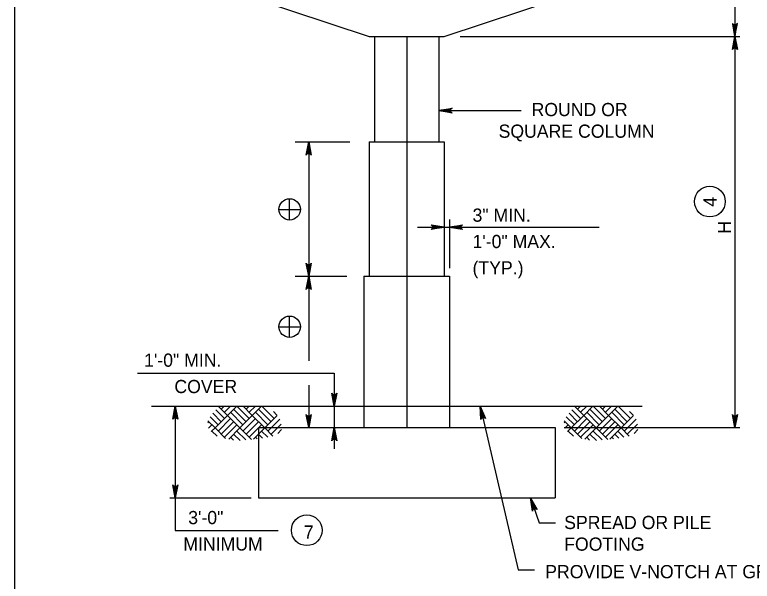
# Model space of a CAD drawing. Extents: x 646165 to 651486, y 296916 to 299292.
# Drawn here: x 649829.6 to 649997.2, y 299095.6 to 299224.4 of the extents above; entities that cross this region are included whole.
import ezdxf

# ---------------------------------------------------------------- set-up
doc = ezdxf.new("R2010")
doc.units = 0
for name, color, linetype in [('2', 7, 'Continuous'), ('34', 7, 'Continuous'), ('50', 7, 'Continuous'), ('51', 7, 'Continuous'), ('52', 7, 'Continuous'), ('53', 7, 'Continuous'), ('54', 7, 'Continuous'), ('56', 7, 'Continuous')]:
    doc.layers.add(name, color=color, linetype=linetype)

msp = doc.modelspace()

# ---------------------------------------------------------------- linework, layer by layer
at = {"layer": '2'}
msp.add_line((649829.59, 298713.25), (649829.59, 299277.25), dxfattribs=at)
at = {"layer": '34'}
msp.add_line((649860.66, 299135.38), (649972.19, 299135.38), dxfattribs=at)
at = {"layer": '50'}
msp.add_line((649918.68, 299219.49), (649918.68, 299130.5), dxfattribs=at)
at = {"layer": '51'}
for p, q in [((649870.68, 299232.6), (649910.16, 299219.49)), ((649927.2, 299219.49), (649966.68, 299232.6)), ((649910.16, 299219.49), (649927.2, 299219.49)), ((649911.36, 299219.49), (649911.36, 299195.49)), ((649926, 299219.49), (649926, 299195.49)), ((649910.16, 299195.49), (649927.2, 299195.49)), ((649910.16, 299195.49), (649910.16, 299164.93)), ((649927.2, 299195.49), (649927.2, 299164.93)), ((649908.96, 299164.93), (649908.96, 299130.5)), ((649908.96, 299164.93), (649928.4, 299164.93)), ((649928.4, 299164.93), (649928.4, 299130.5)), ((649884.96, 299130.5), (649952.41, 299130.5)), ((649884.96, 299130.5), (649884.96, 299114.5)), ((649952.41, 299130.5), (649952.41, 299114.5)), ((649884.96, 299114.5), (649952.41, 299114.5))]:
    msp.add_line(p, q, dxfattribs=at)
at = {"layer": '52'}
for p, q in [((649993.28, 299245.71), (649993.28, 299130.5)), ((649930.87, 299219.49), (649994.38, 299219.49)), ((649893.3, 299195.49), (649905.77, 299195.49)), ((649896.4, 299195.49), (649896.4, 299164.93)), ((649928.4, 299177.87), (649928.4, 299166.82)), ((649921.17, 299176.11), (649962.4, 299176.11)), ((649893.3, 299164.93), (649905.04, 299164.93)), ((649896.4, 299164.93), (649896.4, 299145.67)), ((649857.5, 299142.93), (649902.21, 299142.93)), ((649902.21, 299142.93), (649902.21, 299125.7)), ((649896.4, 299140.16), (649896.4, 299130.5)), ((649866.09, 299135.38), (649866.09, 299107.11)), ((649954.44, 299130.5), (649994.38, 299130.5)), ((649864.85, 299114.5), (649883.32, 299114.5)), ((649866.09, 299107.11), (649889.46, 299107.11))]:
    msp.add_line(p, q, dxfattribs=at)
for points in [[(649993.28, 299219.49), (649993.84, 299222.47), (649993.76, 299222.36), (649993.68, 299222.24), (649993.58, 299222.18), (649993.48, 299222.12), (649993.38, 299222.11), (649993.28, 299222.09), (649993.18, 299222.11), (649993.08, 299222.12), (649992.98, 299222.18), (649992.88, 299222.24), (649992.8, 299222.36), (649992.72, 299222.47), (649993.28, 299219.49), (649992.8, 299222.36), (649992.88, 299222.24), (649993.28, 299219.49), (649992.98, 299222.18), (649993.08, 299222.12), (649993.28, 299219.49), (649993.18, 299222.11), (649993.28, 299222.09), (649993.28, 299219.49), (649993.38, 299222.11), (649993.48, 299222.12), (649993.28, 299219.49), (649993.58, 299222.18), (649993.68, 299222.24), (649993.28, 299219.49), (649993.76, 299222.36)], [(649993.28, 299219.49), (649993.84, 299216.51), (649993.76, 299216.62), (649993.68, 299216.74), (649993.58, 299216.79), (649993.48, 299216.85), (649993.38, 299216.87), (649993.28, 299216.89), (649993.18, 299216.87), (649993.08, 299216.85), (649992.98, 299216.79), (649992.88, 299216.74), (649992.8, 299216.62), (649992.72, 299216.51), (649993.28, 299219.49), (649992.8, 299216.62), (649992.88, 299216.74), (649993.28, 299219.49), (649992.98, 299216.79), (649993.08, 299216.85), (649993.28, 299219.49), (649993.18, 299216.87), (649993.28, 299216.89), (649993.28, 299219.49), (649993.38, 299216.87), (649993.48, 299216.85), (649993.28, 299219.49), (649993.58, 299216.79), (649993.68, 299216.74), (649993.28, 299219.49), (649993.76, 299216.62)], [(649926, 299202.64), (649928.99, 299203.2), (649928.87, 299203.12), (649928.76, 299203.04), (649928.7, 299202.94), (649928.64, 299202.84), (649928.62, 299202.74), (649928.6, 299202.64), (649928.62, 299202.54), (649928.64, 299202.44), (649928.7, 299202.34), (649928.76, 299202.24), (649928.87, 299202.16), (649928.99, 299202.08), (649926, 299202.64), (649928.87, 299202.16), (649928.76, 299202.24), (649926, 299202.64), (649928.7, 299202.34), (649928.64, 299202.44), (649926, 299202.64), (649928.62, 299202.54), (649928.6, 299202.64), (649926, 299202.64), (649928.62, 299202.74), (649928.64, 299202.84), (649926, 299202.64), (649928.7, 299202.94), (649928.76, 299203.04), (649926, 299202.64), (649928.87, 299203.12)], [(649926, 299202.64), (649944.71, 299202.64)], [(649896.4, 299195.49), (649896.96, 299192.51), (649896.88, 299192.62), (649896.8, 299192.73), (649896.7, 299192.79), (649896.6, 299192.85), (649896.5, 299192.87), (649896.4, 299192.89), (649896.3, 299192.87), (649896.2, 299192.85), (649896.1, 299192.79), (649896, 299192.73), (649895.92, 299192.62), (649895.84, 299192.51), (649896.4, 299195.49), (649895.92, 299192.62), (649896, 299192.73), (649896.4, 299195.49), (649896.1, 299192.79), (649896.2, 299192.85), (649896.4, 299195.49), (649896.3, 299192.87), (649896.4, 299192.89), (649896.4, 299195.49), (649896.5, 299192.87), (649896.6, 299192.85), (649896.4, 299195.49), (649896.7, 299192.79), (649896.8, 299192.73), (649896.4, 299195.49), (649896.88, 299192.62)], [(649927.2, 299176.11), (649924.22, 299175.55), (649924.33, 299175.63), (649924.45, 299175.71), (649924.51, 299175.81), (649924.57, 299175.91), (649924.59, 299176.01), (649924.6, 299176.11), (649924.59, 299176.21), (649924.57, 299176.31), (649924.51, 299176.41), (649924.45, 299176.51), (649924.33, 299176.59), (649924.22, 299176.67), (649927.2, 299176.11), (649924.33, 299176.59), (649924.45, 299176.51), (649927.2, 299176.11), (649924.51, 299176.41), (649924.57, 299176.31), (649927.2, 299176.11), (649924.59, 299176.21), (649924.6, 299176.11), (649927.2, 299176.11), (649924.59, 299176.01), (649924.57, 299175.91), (649927.2, 299176.11), (649924.51, 299175.81), (649924.45, 299175.71), (649927.2, 299176.11), (649924.33, 299175.63)], [(649928.4, 299176.11), (649931.39, 299176.67), (649931.27, 299176.59), (649931.16, 299176.51), (649931.1, 299176.41), (649931.04, 299176.31), (649931.02, 299176.21), (649931, 299176.11), (649931.02, 299176.01), (649931.04, 299175.91), (649931.1, 299175.81), (649931.16, 299175.71), (649931.27, 299175.63), (649931.39, 299175.55), (649928.4, 299176.11), (649931.27, 299175.63), (649931.16, 299175.71), (649928.4, 299176.11), (649931.1, 299175.81), (649931.04, 299175.91), (649928.4, 299176.11), (649931.02, 299176.01), (649931, 299176.11), (649928.4, 299176.11), (649931.02, 299176.21), (649931.04, 299176.31), (649928.4, 299176.11), (649931.1, 299176.41), (649931.16, 299176.51), (649928.4, 299176.11), (649931.27, 299176.59)], [(649896.4, 299164.93), (649895.84, 299167.92), (649895.92, 299167.8), (649896, 299167.69), (649896.1, 299167.63), (649896.2, 299167.57), (649896.3, 299167.55), (649896.4, 299167.53), (649896.5, 299167.55), (649896.6, 299167.57), (649896.7, 299167.63), (649896.8, 299167.69), (649896.88, 299167.8), (649896.96, 299167.92), (649896.4, 299164.93), (649896.88, 299167.8), (649896.8, 299167.69), (649896.4, 299164.93), (649896.7, 299167.63), (649896.6, 299167.57), (649896.4, 299164.93), (649896.5, 299167.55), (649896.4, 299167.53), (649896.4, 299164.93), (649896.3, 299167.55), (649896.2, 299167.57), (649896.4, 299164.93), (649896.1, 299167.63), (649896, 299167.69), (649896.4, 299164.93), (649895.92, 299167.8)], [(649896.4, 299164.93), (649896.96, 299161.95), (649896.88, 299162.07), (649896.8, 299162.18), (649896.7, 299162.24), (649896.6, 299162.3), (649896.5, 299162.32), (649896.4, 299162.33), (649896.3, 299162.32), (649896.2, 299162.3), (649896.1, 299162.24), (649896, 299162.18), (649895.92, 299162.07), (649895.84, 299161.95), (649896.4, 299164.93), (649895.92, 299162.07), (649896, 299162.18), (649896.4, 299164.93), (649896.1, 299162.24), (649896.2, 299162.3), (649896.4, 299164.93), (649896.3, 299162.32), (649896.4, 299162.33), (649896.4, 299164.93), (649896.5, 299162.32), (649896.6, 299162.3), (649896.4, 299164.93), (649896.7, 299162.24), (649896.8, 299162.18), (649896.4, 299164.93), (649896.88, 299162.07)], [(649902.21, 299135.38), (649901.65, 299138.36), (649901.73, 299138.25), (649901.81, 299138.13), (649901.91, 299138.07), (649902.01, 299138.01), (649902.11, 299138), (649902.21, 299137.98), (649902.31, 299138), (649902.41, 299138.01), (649902.51, 299138.07), (649902.61, 299138.13), (649902.69, 299138.25), (649902.77, 299138.36), (649902.21, 299135.38), (649902.69, 299138.25), (649902.61, 299138.13), (649902.21, 299135.38), (649902.51, 299138.07), (649902.41, 299138.01), (649902.21, 299135.38), (649902.31, 299138), (649902.21, 299137.98), (649902.21, 299135.38), (649902.11, 299138), (649902.01, 299138.01), (649902.21, 299135.38), (649901.91, 299138.07), (649901.81, 299138.13), (649902.21, 299135.38), (649901.73, 299138.25)], [(649866.09, 299135.38), (649866.65, 299132.4), (649866.57, 299132.51), (649866.49, 299132.63), (649866.39, 299132.69), (649866.29, 299132.75), (649866.19, 299132.76), (649866.09, 299132.78), (649865.99, 299132.76), (649865.89, 299132.75), (649865.79, 299132.69), (649865.69, 299132.63), (649865.61, 299132.51), (649865.53, 299132.4), (649866.09, 299135.38), (649865.61, 299132.51), (649865.69, 299132.63), (649866.09, 299135.38), (649865.79, 299132.69), (649865.89, 299132.75), (649866.09, 299135.38), (649865.99, 299132.76), (649866.09, 299132.78), (649866.09, 299135.38), (649866.19, 299132.76), (649866.29, 299132.75), (649866.09, 299135.38), (649866.39, 299132.69), (649866.49, 299132.63), (649866.09, 299135.38), (649866.57, 299132.51)], [(649935.41, 299135.38), (649944.01, 299098.18), (649947.72, 299098.18)], [(649935.41, 299135.38), (649936.63, 299132.6), (649936.42, 299132.79), (649936.2, 299132.86), (649936, 299132.85), (649935.81, 299132.77), (649935.64, 299132.61), (649935.54, 299132.35), (649935.41, 299135.38), (649935.64, 299132.61), (649935.81, 299132.77), (649935.41, 299135.38), (649936, 299132.85), (649936.2, 299132.86), (649935.41, 299135.38), (649936.42, 299132.79)], [(649896.4, 299130.5), (649895.84, 299133.49), (649895.92, 299133.37), (649896, 299133.26), (649896.1, 299133.2), (649896.2, 299133.14), (649896.3, 299133.12), (649896.4, 299133.1), (649896.5, 299133.12), (649896.6, 299133.14), (649896.7, 299133.2), (649896.8, 299133.26), (649896.88, 299133.37), (649896.96, 299133.49), (649896.4, 299130.5), (649896.88, 299133.37), (649896.8, 299133.26), (649896.4, 299130.5), (649896.7, 299133.2), (649896.6, 299133.14), (649896.4, 299130.5), (649896.5, 299133.12), (649896.4, 299133.1), (649896.4, 299130.5), (649896.3, 299133.12), (649896.2, 299133.14), (649896.4, 299130.5), (649896.1, 299133.2), (649896, 299133.26), (649896.4, 299130.5), (649895.92, 299133.37)], [(649993.28, 299130.5), (649992.72, 299133.49), (649992.8, 299133.37), (649992.88, 299133.26), (649992.98, 299133.2), (649993.08, 299133.14), (649993.18, 299133.12), (649993.28, 299133.1), (649993.38, 299133.12), (649993.48, 299133.14), (649993.58, 299133.2), (649993.68, 299133.26), (649993.76, 299133.37), (649993.84, 299133.49), (649993.28, 299130.5), (649993.76, 299133.37), (649993.68, 299133.26), (649993.28, 299130.5), (649993.58, 299133.2), (649993.48, 299133.14), (649993.28, 299130.5), (649993.38, 299133.12), (649993.28, 299133.1), (649993.28, 299130.5), (649993.18, 299133.12), (649993.08, 299133.14), (649993.28, 299130.5), (649992.98, 299133.2), (649992.88, 299133.26), (649993.28, 299130.5), (649992.8, 299133.37)], [(649902.21, 299130.5), (649902.77, 299127.52), (649902.69, 299127.64), (649902.61, 299127.75), (649902.51, 299127.81), (649902.41, 299127.87), (649902.31, 299127.89), (649902.21, 299127.9), (649902.11, 299127.89), (649902.01, 299127.87), (649901.91, 299127.81), (649901.81, 299127.75), (649901.73, 299127.64), (649901.65, 299127.52), (649902.21, 299130.5), (649901.73, 299127.64), (649901.81, 299127.75), (649902.21, 299130.5), (649901.91, 299127.81), (649902.01, 299127.87), (649902.21, 299130.5), (649902.11, 299127.89), (649902.21, 299127.9), (649902.21, 299130.5), (649902.31, 299127.89), (649902.41, 299127.87), (649902.21, 299130.5), (649902.51, 299127.81), (649902.61, 299127.75), (649902.21, 299130.5), (649902.69, 299127.64)], [(649866.09, 299114.5), (649865.53, 299117.49), (649865.61, 299117.37), (649865.69, 299117.26), (649865.79, 299117.2), (649865.89, 299117.14), (649865.99, 299117.12), (649866.09, 299117.1), (649866.19, 299117.12), (649866.29, 299117.14), (649866.39, 299117.2), (649866.49, 299117.26), (649866.57, 299117.37), (649866.65, 299117.49), (649866.09, 299114.5), (649866.57, 299117.37), (649866.49, 299117.26), (649866.09, 299114.5), (649866.39, 299117.2), (649866.29, 299117.14), (649866.09, 299114.5), (649866.19, 299117.12), (649866.09, 299117.1), (649866.09, 299114.5), (649865.99, 299117.12), (649865.89, 299117.14), (649866.09, 299114.5), (649865.79, 299117.2), (649865.69, 299117.26), (649866.09, 299114.5), (649865.61, 299117.37)], [(649946.79, 299114.5), (649948.82, 299108.86), (649952.53, 299108.86)], [(649946.79, 299114.5), (649948.33, 299111.89), (649948.21, 299111.97), (649948.1, 299112.05), (649947.98, 299112.07), (649947.87, 299112.09), (649947.77, 299112.08), (649947.67, 299112.06), (649947.58, 299112.01), (649947.49, 299111.96), (649947.42, 299111.87), (649947.35, 299111.78), (649947.31, 299111.64), (649947.27, 299111.51), (649946.79, 299114.5), (649947.31, 299111.64), (649947.35, 299111.78), (649946.79, 299114.5), (649947.42, 299111.87), (649947.49, 299111.96), (649946.79, 299114.5), (649947.58, 299112.01), (649947.67, 299112.06), (649946.79, 299114.5), (649947.77, 299112.08), (649947.87, 299112.09), (649946.79, 299114.5), (649947.98, 299112.07), (649948.1, 299112.05), (649946.79, 299114.5), (649948.21, 299111.97)]]:
    msp.add_lwpolyline(points, dxfattribs=at)
for centre in [(649987.6, 299181.93), (649895.97, 299107.16)]:
    msp.add_circle(centre, 3.5, dxfattribs=at)
at = {"layer": '54'}
for p, q in [((649892.08, 299177.72), (649892.08, 299182.58)), ((649889.64, 299180.15), (649894.51, 299180.15)), ((649892.08, 299151.02), (649892.08, 299155.88)), ((649889.64, 299153.45), (649894.51, 299153.45))]:
    msp.add_line(p, q, dxfattribs=at)
for centre in [(649892.08, 299180.15), (649892.08, 299153.45)]:
    msp.add_circle(centre, 2.43, dxfattribs=at)
at = {"layer": '56'}
for p, q in [((649877.94, 299133.28), (649875.91, 299135.3)), ((649876.52, 299134.69), (649877.21, 299135.38)), ((649877.23, 299133.99), (649878.62, 299135.38)), ((649877.94, 299133.28), (649880.04, 299135.38)), ((649882.89, 299132.57), (649880.08, 299135.38)), ((649883.59, 299133.28), (649881.49, 299135.38)), ((649882.18, 299134.69), (649882.87, 299135.38)), ((649882.89, 299133.99), (649884.28, 299135.38)), ((649883.59, 299133.28), (649885.69, 299135.38)), ((649888.54, 299132.57), (649885.73, 299135.38)), ((649958.92, 299133.28), (649956.9, 299135.3)), ((649957.51, 299134.69), (649958.19, 299135.38)), ((649958.21, 299133.99), (649959.61, 299135.38)), ((649958.92, 299133.28), (649961.02, 299135.38)), ((649963.87, 299132.57), (649961.06, 299135.38)), ((649964.58, 299133.28), (649962.48, 299135.38)), ((649963.16, 299134.69), (649963.85, 299135.38)), ((649963.87, 299133.99), (649965.26, 299135.38)), ((649964.58, 299133.28), (649966.68, 299135.38)), ((649969.53, 299132.57), (649966.72, 299135.38)), ((649876.52, 299131.86), (649874.62, 299133.76)), ((649877.23, 299132.57), (649875.27, 299134.53)), ((649881.47, 299131.16), (649878.64, 299133.99)), ((649882.18, 299131.86), (649879.35, 299134.69)), ((649887.13, 299131.16), (649884.3, 299133.99)), ((649887.84, 299131.86), (649885.01, 299134.69)), ((649889.18, 299133.35), (649888.37, 299134.16)), ((649888.54, 299133.99), (649888.56, 299134.01)), ((649957.51, 299131.86), (649955.61, 299133.76)), ((649958.21, 299132.57), (649956.25, 299134.53)), ((649962.46, 299131.16), (649959.63, 299133.99)), ((649963.16, 299131.86), (649960.33, 299134.69)), ((649968.11, 299131.16), (649965.28, 299133.99)), ((649968.82, 299131.86), (649965.99, 299134.69)), ((649970.16, 299133.35), (649969.35, 299134.16)), ((649969.53, 299133.99), (649969.55, 299134.01)), ((649875.11, 299130.45), (649873.47, 299132.09)), ((649873.51, 299131.68), (649873.69, 299131.86)), ((649875.81, 299131.16), (649873.98, 299133)), ((649875.11, 299130.45), (649877.94, 299133.28)), ((649875.81, 299129.74), (649878.64, 299132.57)), ((649876.52, 299129.04), (649879.35, 299131.86)), ((649880.76, 299130.45), (649877.94, 299133.28)), ((649880.76, 299130.45), (649883.59, 299133.28)), ((649881.47, 299129.74), (649884.3, 299132.57)), ((649882.18, 299129.04), (649885.01, 299131.86)), ((649886.42, 299130.45), (649883.59, 299133.28)), ((649886.42, 299130.45), (649889.24, 299133.27)), ((649887.13, 299129.74), (649889.83, 299132.44)), ((649956.09, 299130.45), (649954.45, 299132.09)), ((649954.49, 299131.68), (649954.68, 299131.86)), ((649956.8, 299131.16), (649954.96, 299133)), ((649956.09, 299130.45), (649958.92, 299133.28)), ((649956.8, 299129.74), (649959.63, 299132.57)), ((649957.51, 299129.04), (649960.33, 299131.86)), ((649961.75, 299130.45), (649958.92, 299133.28)), ((649961.75, 299130.45), (649964.58, 299133.28)), ((649962.46, 299129.74), (649965.28, 299132.57)), ((649963.16, 299129.04), (649965.99, 299131.86)), ((649967.41, 299130.45), (649964.58, 299133.28)), ((649967.41, 299130.45), (649970.22, 299133.27)), ((649968.11, 299129.74), (649970.81, 299132.44)), ((649873.64, 299130.39), (649874.4, 299131.16)), ((649874.25, 299129.6), (649875.11, 299130.45)), ((649877.49, 299128.06), (649875.11, 299130.45)), ((649877.23, 299128.33), (649880.06, 299131.16)), ((649878.22, 299127.91), (649880.76, 299130.45)), ((649883.4, 299127.82), (649880.76, 299130.45)), ((649882.89, 299128.33), (649885.71, 299131.16)), ((649883.83, 299127.86), (649886.42, 299130.45)), ((649888.28, 299128.59), (649886.42, 299130.45)), ((649887.84, 299129.04), (649890.13, 299131.33)), ((649889.4, 299129.18), (649890.26, 299130.05)), ((649954.62, 299130.39), (649955.38, 299131.16)), ((649955.24, 299129.6), (649956.09, 299130.45)), ((649958.48, 299128.06), (649956.09, 299130.45)), ((649958.21, 299128.33), (649961.04, 299131.16)), ((649959.21, 299127.91), (649961.75, 299130.45)), ((649964.38, 299127.82), (649961.75, 299130.45)), ((649963.87, 299128.33), (649966.7, 299131.16)), ((649964.82, 299127.86), (649967.41, 299130.45)), ((649969.27, 299128.59), (649967.41, 299130.45)), ((649968.82, 299129.04), (649971.12, 299131.33)), ((649970.38, 299129.18), (649971.24, 299130.05)), ((649875.59, 299128.56), (649874.4, 299129.74)), ((649879.29, 299127.69), (649878.64, 299128.33)), ((649880.81, 299127.57), (649879.35, 299129.04)), ((649882.1, 299127.7), (649880.06, 299129.74)), ((649884.69, 299127.94), (649884.3, 299128.33)), ((649885.9, 299128.14), (649885.01, 299129.04)), ((649887.09, 299128.37), (649885.71, 299129.74)), ((649956.57, 299128.56), (649955.38, 299129.74)), ((649960.27, 299127.69), (649959.63, 299128.33)), ((649961.8, 299127.57), (649960.33, 299129.04)), ((649963.09, 299127.7), (649961.04, 299129.74)), ((649965.67, 299127.94), (649965.28, 299128.33)), ((649966.88, 299128.14), (649965.99, 299129.04)), ((649968.07, 299128.37), (649966.7, 299129.74))]:
    msp.add_line(p, q, dxfattribs=at)

# ---------------------------------------------------------------- texts
at = {"layer": '53'}
for s, p in [('ROUND OR', (649947.07, 299201.37)), ('SQUARE COLUMN', (649939.57, 299196.45)), ('3" MIN.', (649933.65, 299177.35)), ('1\'-0" MAX.', (649933.65, 299171.35)), ('(TYP.)', (649933.65, 299165.35)), ('1\'-0" MIN.', (649859, 299144.36)), ('COVER', (649865.88, 299138.36)), (' 3\'-0"', (649867.91, 299108.55)), ('SPREAD OR PILE', (649954.48, 299107.43)), ('7', (649895.31, 299105.26)), ('MINIMUM', (649867.91, 299102.55)), ('FOOTING', (649954.48, 299102.51)), ('PROVIDE V-NOTCH AT GROUND', (649950.17, 299096.25))]:
    msp.add_text(s, height=3, dxfattribs=at).set_placement(p)
for s, p in [('4', (649989.11, 299180.78)), ('H', (649992.41, 299174.61))]:
    msp.add_text(s, height=3, rotation=90, dxfattribs=at).set_placement(p)

doc.saveas('drawing.dxf')
